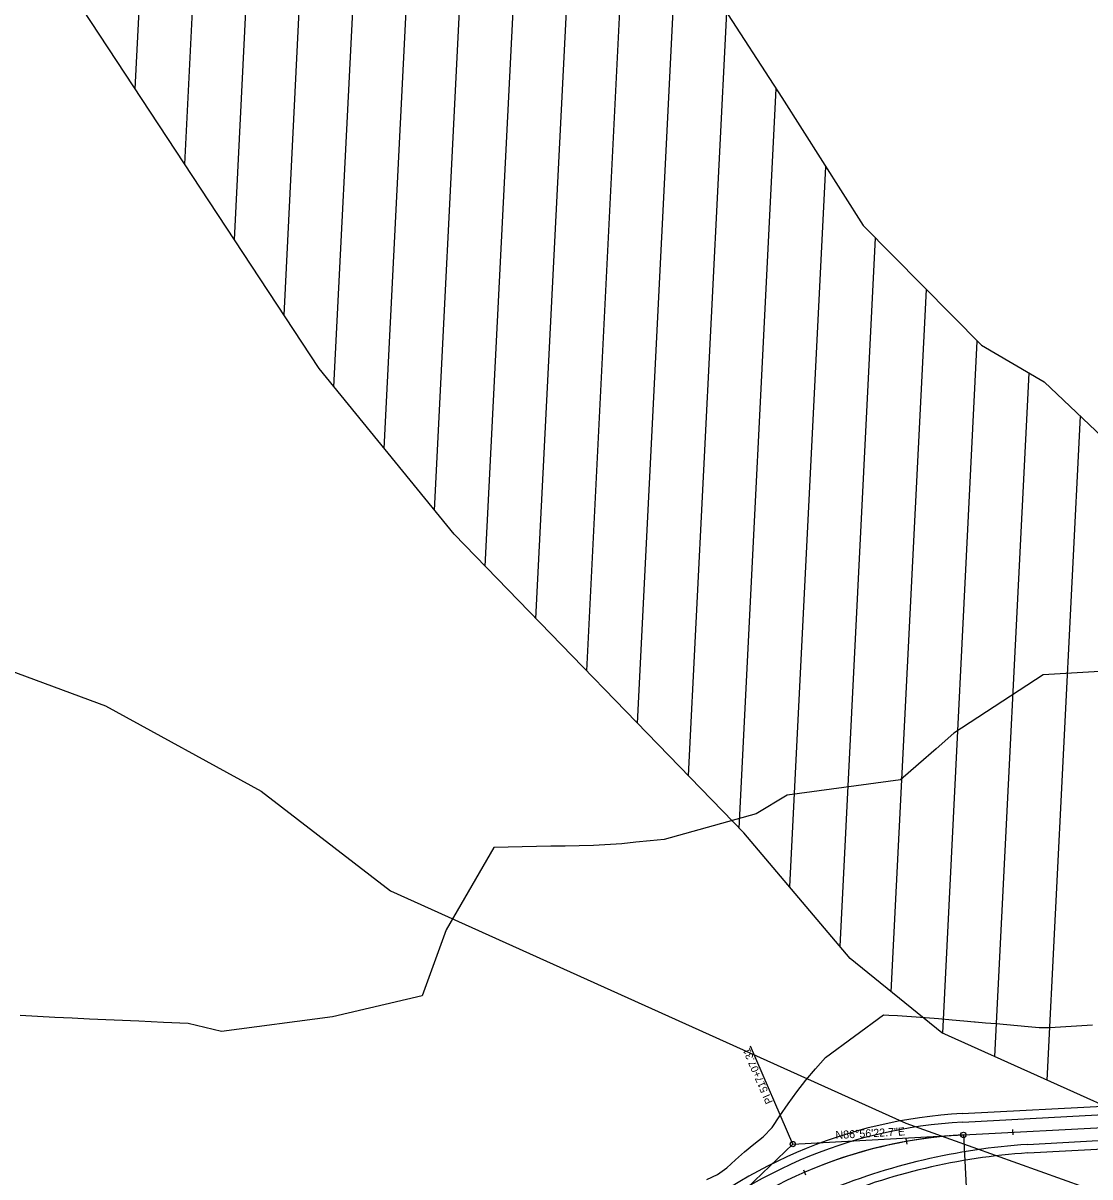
# Model space of a CAD drawing. Extents: x 1300404 to 1323571, y 234004 to 252077.
# Drawn here: x 1309592 to 1310592, y 241789 to 242870 of the extents above; entities that cross this region are included whole.
import ezdxf

# ---------------------------------------------------------------- set-up
doc = ezdxf.new("R2010")
doc.units = 0
for name, color, linetype in [('R_Const Limits', 7, 'Continuous'), ('R_Draft', 7, 'Continuous'), ('R_Floodway', 7, 'Continuous'), ('R_Flooplain', 7, 'Continuous'), ('R_Horz Alg Annot', 7, 'Continuous'), ('R_Horz Alg Annot Leader', 7, 'Continuous'), ('R_Horz Alg Minor Ticks', 7, 'Continuous'), ('R_Horz Alg Tangents', 7, 'Continuous'), ('R_Horz Alg Tangents Text', 7, 'Continuous'), ('R_Lane Edge', 7, 'Continuous'), ('R_Proposed', 7, 'Continuous'), ('R_Shoulder', 7, 'Continuous'), ('T_Drafting', 7, 'Continuous')]:
    doc.layers.add(name, color=color, linetype=linetype)

msp = doc.modelspace()

# ---------------------------------------------------------------- linework, layer by layer
at = {"layer": 'R_Const Limits'}
for points in [[(1310659.8, 242266.4), (1310548.2, 242259.9), (1310464.4, 242205.1), (1310447.8, 242190.6), (1310431.2, 242176.1), (1310414.6, 242161.6), (1310308.2, 242147.2), (1310279.2, 242129.5), (1310193, 242105.7), (1310179.8, 242104.3), (1310166.6, 242102.9), (1310153.4, 242101.6), (1310126.8, 242099.9), (1310113.5, 242099.7), (1310100.1, 242099.4), (1310086.8, 242099.2), (1310073.5, 242098.9), (1310060.1, 242098.6), (1310046.8, 242098.4), (1310033.5, 242098.1), (1309988.7, 242021), (1309966.4, 241959.1), (1309882.3, 241939.5), (1309778.3, 241925.7), (1309762.7, 241929.5), (1309747.1, 241933.3), (1309724, 241934.2), (1309700.9, 241935.2), (1309677.7, 241936.2), (1309654.6, 241937.2), (1309638.3, 241938.1), (1309622, 241938.9), (1309605.8, 241939.8), (1309589.5, 241940.7)], [(1310232.9, 241787.1), (1310242.9, 241791.7), (1310251.8, 241797.9), (1310259.9, 241805.5), (1310268.3, 241813), (1310277, 241820.1), (1310285.9, 241826.9), (1310294.1, 241835.7), (1310301.4, 241846.8), (1310309.1, 241858), (1310317.2, 241869.2), (1310325.7, 241880), (1310334.7, 241890.7), (1310344.1, 241901.3), (1310398.6, 241941.4), (1310403.6, 241941.1), (1310411.7, 241940.6), (1310424.6, 241939.6), (1310437.5, 241938.8), (1310450.2, 241937.7), (1310462.8, 241936.7), (1310473.9, 241935.7), (1310483.9, 241934.8), (1310484.4, 241934.7), (1310494, 241933.9), (1310504, 241933), (1310514.1, 241932.1), (1310524.2, 241931.2), (1310534.2, 241930.3), (1310544.3, 241929.5), (1310554.3, 241929.3), (1310564.3, 241929.9), (1310574.3, 241930.5), (1310584.3, 241931.2), (1310594.2, 241931.8)]]:
    msp.add_lwpolyline(points, dxfattribs=at)
at = {"layer": 'R_Draft'}
msp.add_arc((1310575, 241212.4), 608.9, 93.9267, 112.4996, dxfattribs=at)
at = {"layer": 'R_Floodway'}
for p, q in [((1309697.3, 242809), (1309735, 243561.9)), ((1309743.8, 242738.2), (1309782.9, 243518.6)), ((1309790.3, 242667.5), (1309831.1, 243481.3)), ((1309836.8, 242596.7), (1309878.7, 243432)), ((1309883.5, 242529.8), (1309925.7, 243372)), ((1309930.7, 242471.9), (1309972.5, 243305.9)), ((1309977.9, 242414.1), (1310019.2, 243239.8)), ((1310025.3, 242361.6), (1310066, 243173.7)), ((1310072.9, 242312.6), (1310112.7, 243106.8)), ((1310120.5, 242263.5), (1310158.6, 243023.4)), ((1310168.1, 242214.5), (1310204.9, 242949.2)), ((1310215.7, 242165.4), (1310251.6, 242880.6)), ((1310263.3, 242116.3), (1310298, 242808.9)), ((1310310.6, 242061.1), (1310344.4, 242736.1)), ((1310357.9, 242005.2), (1310391.1, 242669.1)), ((1310405.8, 241962.9), (1310438.8, 242620.8)), ((1310454, 241924.2), (1310486.4, 242572.5)), ((1310502.9, 241902.2), (1310535, 242542.5)), ((1310551.9, 241880.2), (1310583, 242502.1))]:
    msp.add_line(p, q, dxfattribs=at)
for points in [[(1312719.3, 241174), (1312375.3, 241167.2), (1311696.9, 241341.7), (1311497.5, 241419.5), (1311333.8, 241508.8), (1311059.1, 241652.1), (1310740.8, 241795.1), (1310453.3, 241924.5), (1310367.2, 241994.2), (1310267.8, 242111.7), (1309996.2, 242391.6), (1309869.7, 242546.7), (1309624.5, 242919.6)], [(1310244.9, 242890.8), (1310303.3, 242800.7), (1310379.6, 242680.8), (1310490.2, 242568.7), (1310549, 242534.3), (1310676, 242414.2), (1310731.6, 242363), (1310810.3, 242291.3), (1310887.6, 242241.4), (1310974.9, 242195.9), (1311031.6, 242168.8), (1311109.7, 242133.4), (1311173.8, 242108.4), (1311242.7, 242083.2), (1311339.3, 242032.3), (1311351, 242024.5), (1311431.5, 241940.6), (1311405.2, 241750.8)]]:
    msp.add_lwpolyline(points, dxfattribs=at)
at = {"layer": 'R_Flooplain'}
msp.add_lwpolyline([(1308850.4, 242983.4), (1308921.9, 242863.7), (1309009.8, 242685), (1309044.1, 242596.2), (1309055.9, 242542.4), (1309352.1, 242367.8), (1309503.2, 242292.4), (1309669.5, 242230.8), (1309815.5, 242150.9), (1309936.7, 242057.6), (1310419.4, 241839.8), (1310733.2, 241727.2), (1311043.7, 241597.8), (1311103.2, 241577.9), (1311152.8, 241553.6), (1311178, 241525.7), (1311328.5, 241486.7), (1311553.1, 241381), (1311870.3, 241290), (1312137.5, 241213.6), (1312460.1, 241035.3)], dxfattribs=at)
at = {"layer": 'R_Horz Alg Annot Leader'}
for points in [[(1310313.6, 241820.2), (1310273.9, 241912)], [(1310473.4, 241828.8), (1310479.2, 241719.2)]]:
    msp.add_lwpolyline(points, dxfattribs=at)
at = {"layer": 'R_Horz Alg Minor Ticks'}
for points in [[(1310519.4, 241833.7), (1310519.6, 241828.7)], [(1310419.5, 241825), (1310420.4, 241820.1)], [(1310323.5, 241796), (1310325.4, 241791.4)]]:
    msp.add_lwpolyline(points, dxfattribs=at)
at = {"layer": 'R_Horz Alg Tangents'}
for p, q in [((1310313.6, 241820.2), (1310473.4, 241828.8)), ((1310197.9, 241709.8), (1310313.6, 241820.2))]:
    msp.add_line(p, q, dxfattribs=at)
at = {"layer": 'R_Lane Edge'}
for p, q in [((1310472.7, 241840.7), (1310917.8, 241864.5)), ((1310533.3, 241819.9), (1310919, 241840.6))]:
    msp.add_line(p, q, dxfattribs=at)
for centre, radius, start, end in [((1310496.4, 241397), 444.4, 93.0604, 133.6667), ((1310575, 241212.4), 608.9, 93.9267, 112.4996)]:
    msp.add_arc(centre, radius, start, end, dxfattribs=at)
at = {"layer": 'R_Proposed'}
msp.add_line((1310473.4, 241828.8), (1310918.4, 241852.6), dxfattribs=at)
for centre in [(1310313.6, 241820.2), (1310473.4, 241828.8)]:
    msp.add_circle(centre, 2.5, dxfattribs=at)
for start, end in [(93.0604, 133.6667), (93.0604, 111.6332), (94.9846, 111.6332), (94.9846, 111.6332)]:
    msp.add_arc((1310496.4, 241397), 432.4, start, end, dxfattribs=at)
at = {"layer": 'R_Shoulder'}
for p, q in [((1310472.3, 241848.7), (1310917.3, 241872.5)), ((1310533.7, 241812), (1310919.5, 241832.6))]:
    msp.add_line(p, q, dxfattribs=at)
for centre, radius, start, end in [((1310496.4, 241397), 452.4, 93.0604, 133.6667), ((1310575, 241212.4), 600.9, 93.9325, 112.5014)]:
    msp.add_arc(centre, radius, start, end, dxfattribs=at)
at = {"layer": 'T_Drafting'}
msp.add_line((1310473.4, 241828.8), (1310918.4, 241852.6), dxfattribs=at)

# ---------------------------------------------------------------- texts
at = {"layer": 'R_Horz Alg Annot'}
msp.add_text('PI 517+07.31', height=7, rotation=113.3635, dxfattribs=at).set_placement((1310295, 241859.6))
at = {"layer": 'R_Horz Alg Tangents Text'}
msp.add_text('N86%%d56\'22.7"E', height=7.5, rotation=3.0604, dxfattribs=at).set_placement((1310353.7, 241824.9))

doc.saveas('drawing.dxf')
